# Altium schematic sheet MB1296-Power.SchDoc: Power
size A4; Date: 25-JAN-2017; Organization: STMicroelectronics; Address1: Microcontrollers Division; Address2: 190, avenue Célestin COQ; Address3: 13106 ROUSSET Cedex; Address4: FRANCE; DocumentNumber: MB1296; Revision: D-01; SheetNumber: 2; SheetTotal: 6; Project: STM32 LoRa Discovery
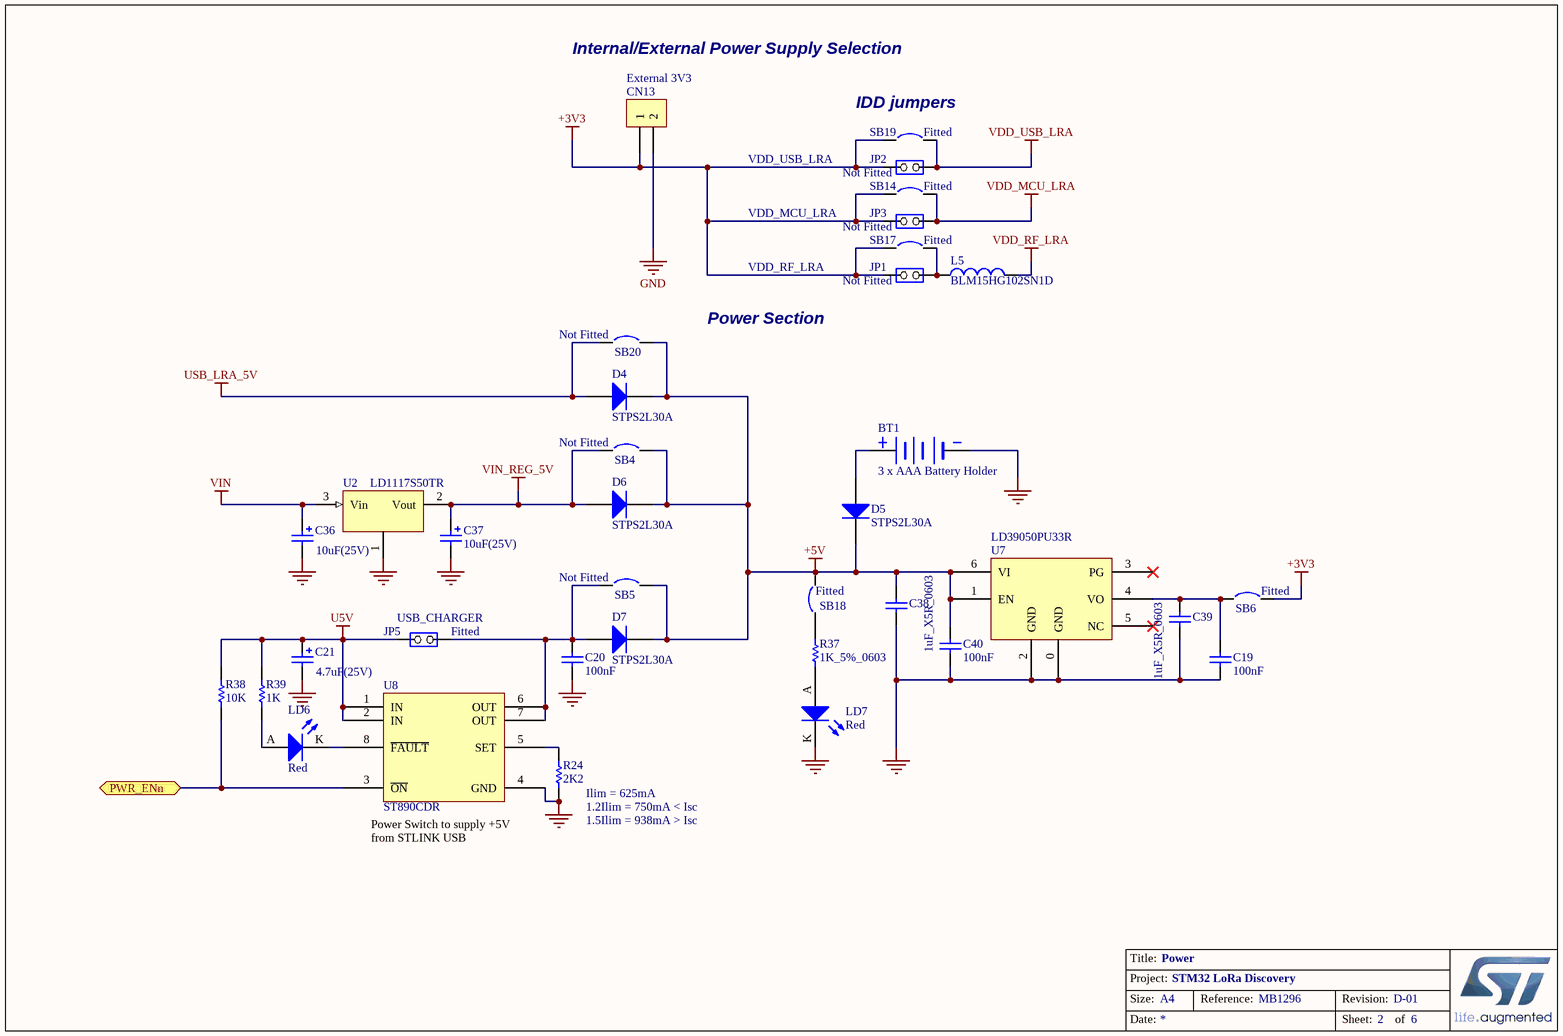
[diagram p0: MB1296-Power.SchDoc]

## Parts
BT1  3 x AAA Battery Holder  [3 X AAA Battery Holder]
C19  100nF  [0603C]
C20  100nF  [0603C]
C21  4.7uF(25V)  [TAN-B]
C36  10uF(25V)  [TAN-B]
C37  10uF(25V)  [TAN-B]
C38  1uF_X5R_0603  [0603C]
C39  1uF_X5R_0603  [0603C]
C40  100nF  [0603C]
CN13  External 3V3  [SIP2]
D4  STPS2L30A  [SMA]
D5  STPS2L30A  [SMA]
D6  STPS2L30A  [SMA]
D7  STPS2L30A  [SMA]
JP1  VDD_RF_LRA  [SIP2/2.54]
JP2  VDD_USB_LRA  [SIP2/2.54]
JP3  VDD_MCU_LRA  [SIP2/2.54]
JP5  USB_CHARGER  [SIP2/2.54]
L5  BLM15HG102SN1D  [0402]
LD6  Red  [0603D]
LD7  Red  [0603D]
R24  2K2  [0603R]
R37  1K_5%_0603  [0603]
R38  10K  [0603R]
R39  1K  [0603R]
SB4  Circuit Breaker  [JP2_SMD]  (value not drawn)
SB5  Circuit Breaker  [JP2_SMD]  (value not drawn)
SB6  Circuit Breaker  [JP2_SMD]  (value not drawn)
SB14  Circuit Breaker  [JP2_SMD]  (value not drawn)
SB17  Circuit Breaker  [JP2_SMD]  (value not drawn)
SB18  Circuit Breaker  [JP2_SMD]  (value not drawn)
SB19  Circuit Breaker  [JP2_SMD]  (value not drawn)
SB20  Circuit Breaker  [JP2_SMD]  (value not drawn)
U2  LD1117S50TR  [SOT-223]
U7  LD39050PU33R  [DFN6(3X3)]
U8  ST890CDR  [SOIC8_1R27_4R9X6]

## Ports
PWR_ENn

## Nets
+3V3: CN13.1 JP1.2(NO) JP2.2(NO) JP3.2(NO) SB6.2 SB14.1 SB17.1 SB19.1
+5V: C38.2 C40.2 D4.2(K) D5.2(K) D6.2(K) D7.2(K) SB4.2 SB5.2 SB18.2 SB20.2 U7.1(EN) U7.6(VI)
GND: BT1.2(-) C19.1 C20.1 C21.2 C36.2 C37.2 C38.1 C39.1 C40.1 CN13.2 LD7.K R24.2 U2.1 U7.0(GND) U7.2(GND) U8.4(GND)
U5V: C21.1 JP5.2(NO) R38.2 R39.2 U8.1(IN) U8.2(IN)
USB_LRA_5V: D4.1(A) SB20.1
VDD_MCU_LRA: JP3.1(COMMON) SB14.2
VDD_RF_LRA: L5.2
VDD_USB_LRA: JP2.1(COMMON) SB19.2
VIN: C36.1 U2.3(Vin)
VIN_REG_5V: C37.1 D6.1(A) SB4.1 U2.2(Vout)
PWR_ENn: R38.1 U8.3(~{ON}) ; port PWR_ENn
NetBT1_1: BT1.1(+) D5.1(A)
NetC19_2: C19.2 C39.2 SB6.1 U7.4(VO)
NetC20_2: C20.2 D7.1(A) JP5.1(COMMON) SB5.1 U8.6(OUT) U8.7(OUT)
NetJP1_1: JP1.1(COMMON) L5.1 SB17.2
NetLD6_A: LD6.A R39.1
NetLD6_K: LD6.K U8.8(~{FAULT})
NetLD7_A: LD7.A R37.1
NetR24_1: R24.1 U8.5(SET)
NetR37_2: R37.2 SB18.1

Not connected (* = marked no-connect by the designer): U7 3(PG)* 5(NC)*

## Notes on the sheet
- Internal/External Power Supply Selection
- (near SB19) IDD jumpers
- (near JP2) Not Fitted
- (near SB19) Fitted
- (near JP3) Not Fitted
- (near SB17) Fitted
- (near SB14) Fitted
- (near JP1) Not Fitted
- (near SB20) Not Fitted
- Power Section
- (near SB4) Not Fitted
- (near SB5) Not Fitted
- (near JP5) Fitted
- (near SB18) Fitted
- (near SB6) Fitted
- Power Switch to supply +5V from STLINK USB
- (near R24) Ilim = 625mA
- (near R24) 1.2Ilim = 750mA < Isc
- (near R24) 1.5Ilim = 938mA > Isc

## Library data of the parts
BT1 = 3 x AAA Battery Holder: Manufacturer: Keystone; Manufacturer P/N: 2479
C19 C20 C40 = CAP: Capacitor 100nF; Manufacturer: YAGEO; Manufacturer P/N: CC0603KRX7R9BB104; Provided by: Subcon
C21 = Cap Pol1: Polarized Capacitor (Radial); Manufacturer: YAGEO; Manufacturer P/N: CC1206KKX7R8BB475; Provided by: Subcon
C36 C37 = Cap Pol1: Polarized Capacitor (Radial); Manufacturer: AVX; Manufacturer P/N: TAJB106K025R; Provided by: Subcon
C38 C39 = CAP SMD 0603  X5R 1µF 25V 10%: 0603  X5R 1µF; Manufacturer: YAGEO; Manufacturer P/N: CC0603KRX5R7BB105; Provided by: Subcon
CN13 = Header 2: Manufacturer: Kontek; Manufacturer P/N: 4710334140400; Order Code RS: 423-2835; Provided by: Subcon
D4-D7 = STPS2L30A: Provided by: STM; Order: BAT60JFILM; ECCN_US/EU: EAR99/NEC
JP1-JP3 JP5 = JP2: Manufacturer: Lyconn; Manufacturer P/N: 313140S111116; Fitted: No; Provided by: Subcon
L5 = BLM15HG102SN1D: Manufacturer: Murata Electronics
LD6 LD7 = LED2: Typical RED, GREEN, YELLOW, AMBER GaAs LED; Manufacturer: Everlight; Manufacturer P/N  Green: 19-213SY6C/S530-E2/TR8LED; Manufacturer P/N  Red: 19-213-R6C-AP1Q2B-3T
R24 = Res1_2: Resistor; Manufacturer: YAGEO; Manufacturer P/N: RC0603FR-072K2L; Provided by: Subcon; Value: 2K7
R37 = RES SMD 0603 1K 50V 5% 0.063W: 0603 1K 50V 5% 0.063W; Manufacturer: YAGEO; Manufacturer P/N: RC0603FR-071KL; Order code RS: 461-3818; Provided by: Subcon
R38 = Resistor_ST: Resistor 0603; Manufacturer: YAGEO; Manufacturer P/N: RC0603JR-0710KL; Provided by: Subcon
R39 = Resistor_ST: Resistor 0603; Manufacturer: YAGEO; Manufacturer P/N: RC0603FR-071KL; Provided by: Subcon
SB4 SB5 SB20 = Circuit Breaker: Fitted: No
SB6 SB14 SB17-SB19 = Circuit Breaker: Fitted: Yes
U2 = LD1117: Manufacturer: ST; ECCN_US/UE: EAR99/NEC; Provided by: STM
U7 = LD39050P: Manufacturer: ST; ECCN_US/UE: EAR99/NEC; Provided by: STM
U8 = ST890CDR: Manufacturer: ST; Manufacturer P/N: ST890R; ECCN_US/UE: EAR99/NEC; Provided by: STM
